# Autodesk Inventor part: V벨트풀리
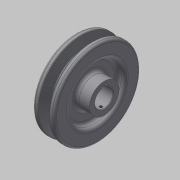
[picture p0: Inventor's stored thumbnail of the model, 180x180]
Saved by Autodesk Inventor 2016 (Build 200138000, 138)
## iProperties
Created: 2015-11
Part Number: V벨트풀리
Material: 강철, 탄소
Document SubType Name: Modeling
Designer: mduedu
Density: 1 g/cm^3
Appearance: 기본값
Author: mduedu
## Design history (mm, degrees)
sketch "스케치1"
  geometry: L1 (-9.5, 0)-(9.5, 0); L2 (0, 0)-(0, 37.7); L3 (-4.825, 37.7)-(-9.5, 37.7); L4 (-9.5, 37.7)-(-9.5, 0); L5 (0, 28.7)-(-2.074, 28.7); L6 (-2.074, 28.7)-(-4.825, 37.7); L7 (4.825, 37.7)-(9.5, 37.7); L8 (9.5, 37.7)-(9.5, 0); L9 (0, 28.7)-(2.074, 28.7); L10 (2.074, 28.7)-(4.825, 37.7); L11 (-9.5, 35)-(9.5, 35); 3 further points
  constraints: 22 end point, 7 point on line, 4 perpendicular, 3 symmetric about line, 1 coincident, 1 horizontal, 1 horizontal alignment, 1 midpoint, 1 vertical
  dimensions: "d0" = 19 distance of L1.start L1.end; "d2" = 75.4 diameter of L2.end L1 (derived); "d3" = 34 deg angle of L10 L6; "d4" = 6.3 distance between parallel lines of L11 L9; "d5" = 2.7 distance between parallel lines of L7 L11; "d6" = 8 distance of point (4, 35) point (-4, 35); "d7" = 70 diameter of L11 L1
revolve "회전1" sketch "스케치1" stored, may be unused: angle "d8" = 90 deg
sketch "스케치2"
  geometry: C1 r 24 at (0, 0); C2 r 13 at (0, 0); 1 further point
  constraints: 2 centre point, 2 coincident
  dimensions: "d9" = 48 diameter of C1; "d10" = 26 diameter of C2
extrude "돌출1" cut sketch "스케치2" distance "d11" = 6; taper "d12" = 0 deg
extrude "돌출3" join sketch "스케치2" distance "d37" = 6; taper "d38" = 0 deg
fillet "모깎기1" dims "d13" = 3
fillet "모깎기2" dims "d14" = 3
fillet "모깎기3" dims "d15" = 1, "d16" = 0.5, "d17" = 2
hole "구멍1" diameter "d20" = 16; stored, may be unused: countersink angle "d24" = 90 deg, drill point angle "d26" = 118 deg; dims "d21" = 6, "d22" = 4, "d23" = 2, "d25" = 8, "d53" = 10, "d54" = 10
sketch "스케치3"
  geometry: L1 (-2.5, 0)-(2.5, 0); L2 (2.5, 0)-(2.5, 10.3); L3 (2.5, 10.3)-(-2.5, 10.3); L4 (-2.5, 10.3)-(-2.5, 0); 2 further points
  constraints: 8 end point, 2 parallel, 1 coincident, 1 horizontal, 1 midpoint, 1 perpendicular
  dimensions: "d27" = 5 distance of L2.end L3.end; "d29" = 10.3 distance of L3.end L1.start
extrude "돌출2" cut sketch "스케치3" stored distance "d30" = 6; taper "d31" = 0 deg
node "작업 평면1"
sketch "스케치4"
  geometry: L1 (19, -27)-(19, 27) reference; 2 further points
  constraints: 1 horizontal alignment
  dimensions: "d52" = 22 distance from line of L1 point (-3, 0)
hole "구멍2" sketch "스케치4" at (-3, 0) diameter "d42" = 2.459; stored, may be unused: countersink angle "d46" = 90 deg, drill point angle "d48" = 118 deg; dims "d43" = 6, "d44" = 4, "d45" = 2, "d47" = 8
chamfer "모따기3" distance "d58" = 0.5; stored, may be unused: second distance "d59" = 2, angle "d60" = 45 deg
node "솔리드1"
mirror "대칭1"
